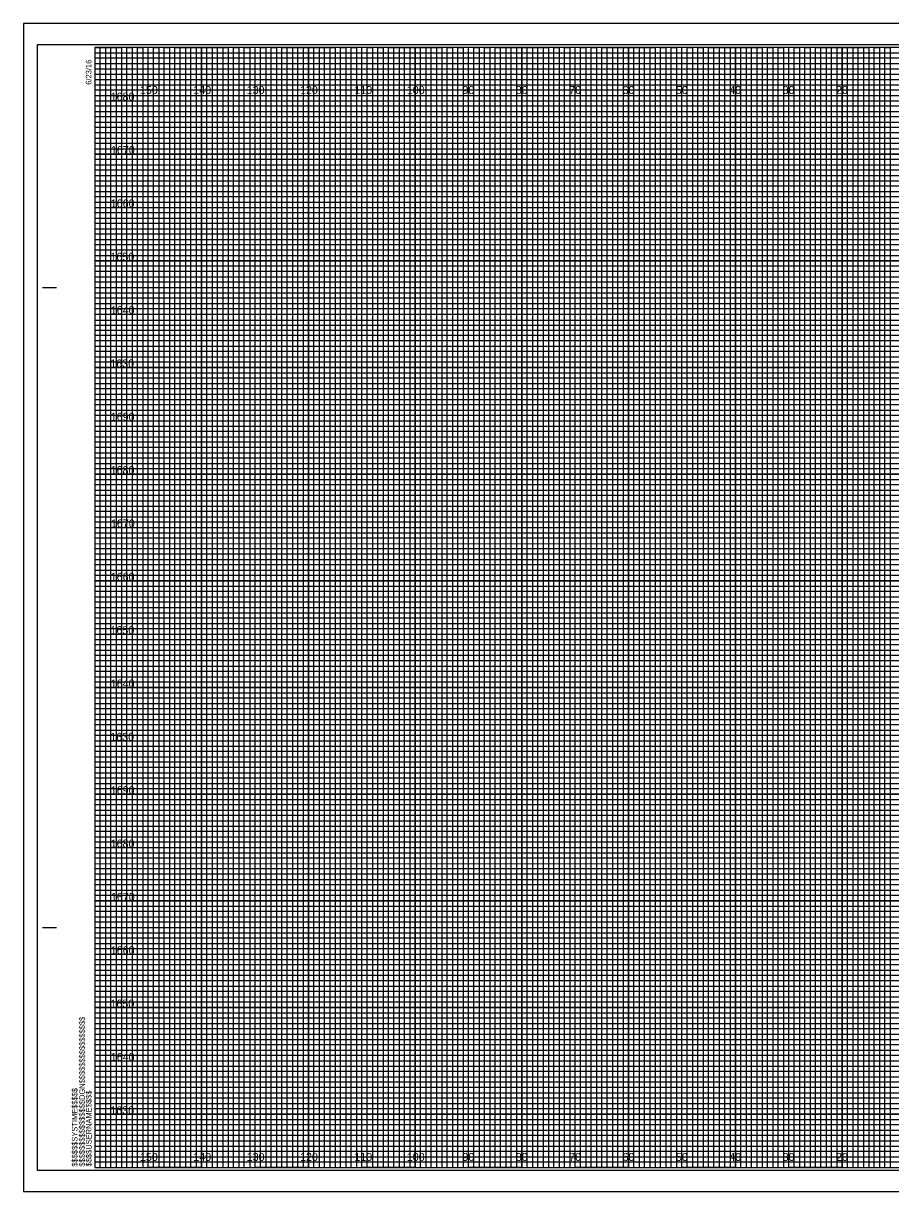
# Model space of a CAD drawing. Extents: x -13 to 323, y -5 to 2414.
# Drawn here: x -13.4 to 149.1, y 655.5 to 874.5 of the extents above; entities that cross this region are included whole.
import ezdxf

# ---------------------------------------------------------------- set-up
doc = ezdxf.new("R2010")
doc.units = 0
for name, color, linetype in [('Prop XS Elevation Labels', 7, 'Continuous'), ('Prop XS Offset Labels', 7, 'Continuous'), ('Sheet Cross Section CELL', 7, 'Continuous'), ('Sheet Cross Section Grid Major CELL', 7, 'Continuous'), ('Sheet Cross Section Grid Middle CELL', 7, 'Continuous'), ('Sheet Cross Section Grid Minor 1 CELL', 7, 'Continuous'), ('Sheet Cross Section Grid Minor 2 CELL', 7, 'Continuous'), ('Sheet Cutting Line CELL', 7, 'Continuous'), ('Sheet DOT Grid CELL', 7, 'Continuous'), ('Sheet Plot Border Inside CELL', 7, 'Continuous'), ('Sheet Plot Border Outside CELL', 7, 'Continuous')]:
    doc.layers.add(name, color=color, linetype=linetype)

msp = doc.modelspace()

# ---------------------------------------------------------------- linework, layer by layer
at = {"layer": 'Sheet Cross Section CELL'}
for p, q in [((-9.8, 825), (-7.3, 825)), ((-9.7, 825), (-7.2, 825)), ((-9.8, 705), (-7.3, 705)), ((-9.7, 705), (-7.2, 705)), ((0, 660), (0, 660)), ((0, 660), (0, 660)), ((0, 660), (0, 660)), ((0, 660), (0, 660)), ((0, 660), (0, 660)), ((0, 660), (0, 660)), ((0, 660), (0, 660))]:
    msp.add_line(p, q, dxfattribs=at)
msp.add_lwpolyline([(320, 870), (0, 870), (0, 660), (320, 660)], close=True, dxfattribs=at)
at = {"layer": 'Sheet Cross Section Grid Major CELL'}
for p, q in [((10, 870), (0, 870)), ((10, 660), (10, 870)), ((30, 870), (20, 870)), ((20, 870), (20, 660)), ((30, 660), (30, 870)), ((50, 870), (40, 870)), ((40, 870), (40, 660)), ((50, 660), (50, 870)), ((70, 870), (60, 870)), ((60, 870), (60, 660)), ((70, 660), (70, 870)), ((90, 870), (80, 870)), ((80, 870), (80, 660)), ((90, 660), (90, 870)), ((110, 870), (100, 870)), ((100, 870), (100, 660)), ((110, 660), (110, 870)), ((130, 870), (120, 870)), ((120, 870), (120, 660)), ((130, 660), (130, 870)), ((150, 870), (140, 870)), ((140, 870), (140, 660)), ((20, 660), (10, 660)), ((40, 660), (30, 660)), ((60, 660), (50, 660)), ((80, 660), (70, 660)), ((100, 660), (90, 660)), ((120, 660), (110, 660)), ((140, 660), (130, 660))]:
    msp.add_line(p, q, dxfattribs=at)
for points in [[(0, 860), (320, 860), (320, 850), (0, 850)], [(0, 840), (320, 840), (320, 830), (0, 830)], [(0, 820), (320, 820), (320, 810), (0, 810)], [(0, 800), (320, 800), (320, 790), (0, 790)], [(0, 780), (320, 780), (320, 770), (0, 770)], [(0, 760), (320, 760), (320, 750), (0, 750)], [(0, 740), (320, 740), (320, 730), (0, 730)], [(0, 720), (320, 720), (320, 710), (0, 710)], [(0, 700), (320, 700), (320, 690), (0, 690)], [(0, 680), (320, 680), (320, 670), (0, 670)]]:
    msp.add_lwpolyline(points, dxfattribs=at)
at = {"layer": 'Sheet Cross Section Grid Middle CELL'}
for points in [[(0, 870), (5, 870), (5, 660), (15, 660), (15, 870), (25, 870), (25, 660), (35, 660), (35, 870), (45, 870), (45, 660), (55, 660), (55, 870), (65, 870), (65, 660), (75, 660), (75, 870), (85, 870), (85, 660), (95, 660), (95, 870), (105, 870), (105, 660), (115, 660), (115, 870), (125, 870), (125, 660), (135, 660), (135, 870), (145, 870), (145, 660), (155, 660)], [(0, 865), (275, 865)], [(0, 845), (320, 845), (320, 855), (0, 855)], [(0, 825), (320, 825), (320, 835), (0, 835)], [(0, 805), (320, 805), (320, 815), (0, 815)], [(0, 785), (320, 785), (320, 795), (0, 795)], [(0, 765), (320, 765), (320, 775), (0, 775)], [(0, 745), (320, 745), (320, 755), (0, 755)], [(0, 725), (320, 725), (320, 735), (0, 735)], [(0, 705), (320, 705), (320, 715), (0, 715)], [(0, 685), (320, 685), (320, 695), (0, 695)], [(0, 665), (320, 665), (320, 675), (0, 675)]]:
    msp.add_lwpolyline(points, dxfattribs=at)
at = {"layer": 'Sheet Cross Section Grid Minor 1 CELL'}
for p, q in [((0, 869), (260, 869)), ((260, 867.98), (0, 867.98)), ((0, 867.98), (0, 867)), ((0, 867), (260, 867)), ((260, 865.89), (0, 865.89)), ((0, 865.89), (0, 864)), ((0, 864), (320, 864))]:
    msp.add_line(p, q, dxfattribs=at)
for points in [[(0, 863), (270, 863), (320, 863), (320, 862), (0, 862)], [(0, 861), (320, 861), (320, 859), (0, 859)], [(0, 858), (320, 858), (320, 857), (0, 856.98)], [(0, 856), (320, 856), (320, 854), (0, 854)], [(0, 853), (320, 853), (320, 852), (0, 852)], [(0, 851), (320, 851), (320, 849), (0, 849)], [(0, 848), (320, 848), (320, 847), (0, 847)], [(0, 846), (320, 846), (320, 844), (0, 844)], [(0, 843), (320, 843), (320, 842), (0, 842)], [(0, 841), (320, 841), (320, 839), (0, 839)], [(0, 838), (320, 838), (320, 837), (0, 837)], [(0, 836), (320, 836), (320, 833.95), (320, 833), (320, 832), (0, 832)], [(0, 834), (320, 834), (320, 833), (0, 833)], [(0, 831), (320, 831), (320, 829), (0, 829.03)], [(0, 829.03), (320, 829), (320, 828), (0, 828)], [(0, 827), (320, 827), (320, 826), (0, 826)], [(0, 824), (320, 824), (320, 823), (0, 823)], [(0, 822), (320, 822), (320, 821), (0, 821)], [(-0.07, 818.89), (320, 818.89), (320, 817.88), (-0.07, 817.88)], [(0, 817), (320, 817), (320, 816), (0, 816)], [(0, 814), (320, 814), (320, 813), (0, 813)], [(0, 812), (320, 812), (320, 811), (0, 811)], [(0, 809), (320, 809), (320, 808), (0, 808)], [(0, 807), (320, 807), (320, 806), (0, 806)], [(0, 804), (320, 804), (320, 803), (0, 803)], [(0, 802), (320, 802), (320, 801), (0, 801)], [(0, 799), (320, 799), (319.99, 797.98), (0, 798)], [(0, 797), (320, 797), (320, 796), (0, 796)], [(0, 794), (320, 794), (320, 793), (0, 793)], [(0, 792), (320, 792), (320, 791), (0, 791)], [(0, 789), (320, 789), (320, 788), (0, 788)], [(0, 787), (320, 787), (320, 786), (0, 786)], [(0, 784), (320, 784), (320, 783), (0, 783)], [(0, 782), (320, 782), (320, 781), (0, 781)], [(0, 779), (320, 779), (320, 778), (0, 778)], [(0, 776.99), (320.07, 776.91), (320, 776), (0, 776)], [(0, 774), (320, 774), (320, 773), (0, 773)], [(0, 772), (320, 772), (320, 771), (0, 771)], [(0, 769), (320, 769), (320, 768), (0, 768)], [(0, 767), (320, 767), (320, 766), (0, 766)], [(0, 764), (320, 764), (320, 763), (0, 763)], [(0, 762), (320, 762), (320, 761), (0, 761)], [(0, 759), (320, 759), (320, 758), (0, 758)], [(0, 757), (320, 757), (320, 756), (0, 756)], [(0, 754), (320, 754), (320, 753), (0, 753)], [(0, 752), (320, 752), (320, 751), (0, 751)], [(0, 749), (320, 749), (320, 748), (0, 748)], [(0, 747), (320, 747), (320, 746), (0, 746)], [(0, 744), (320, 744), (320, 743), (0, 743)], [(0, 742), (320, 742), (320, 741), (0, 741)], [(0, 739), (320, 739), (319.99, 737.98), (0, 738)], [(0, 737), (320, 737), (320, 736), (0, 736)], [(0, 734), (320, 734), (320, 733), (0, 733)], [(0, 732), (320, 732), (320, 731), (0, 731)], [(0, 729), (320, 729), (320, 728), (0, 728)], [(0, 727), (320, 727), (320, 726), (0, 726)], [(0, 724), (320, 724), (320, 723), (0, 723)], [(0, 722), (320, 722), (320, 721), (0, 721)], [(0, 719), (320, 719), (320, 718), (0, 718)], [(0, 716.99), (320.07, 716.91), (320, 716), (0, 716)], [(0, 714), (320, 714), (320, 713), (0, 713)], [(0, 712), (320, 712), (320, 711), (0, 711)], [(0, 709), (320, 709), (320, 708), (0, 708)], [(0, 707), (320, 707), (320, 706), (0, 706)], [(0, 704), (320, 704), (320, 703), (0, 703)], [(0, 702), (320, 702), (320, 701), (0, 701)], [(0, 699), (320, 699), (320, 698), (0, 698)], [(0, 697), (320, 697), (320, 696), (0, 696)], [(0, 694), (320, 694), (320, 693), (0, 693)], [(0, 692), (320, 692), (320, 691), (0, 691)], [(0, 689), (320, 689), (320, 688), (0, 688)], [(0, 687), (320, 687), (320, 686), (0, 686)], [(0, 684), (320, 684), (320, 683), (0, 683)], [(0, 682), (320, 682), (320, 681), (0, 681)], [(0, 679), (320, 679), (320, 678), (0, 678)], [(0, 677), (320, 677), (320, 676), (0, 676)], [(0, 674), (320, 674), (320, 673), (0, 673)], [(0, 672), (320, 672), (320, 671), (0, 671)], [(0, 669), (320, 669), (320, 668), (0, 668)], [(0, 667), (320, 667), (320, 666), (0, 666)], [(0, 664), (320, 664), (320, 663), (0, 663)], [(0, 662), (320, 662), (320, 661), (0, 661)]]:
    msp.add_lwpolyline(points, dxfattribs=at)
at = {"layer": 'Sheet Cross Section Grid Minor 2 CELL'}
for points in [[(0, 660), (1, 660), (1, 870), (2, 870), (2, 660)], [(2, 660), (3, 660), (3, 870), (4, 870), (4, 660)], [(5, 660), (6, 660), (6, 870), (7, 870), (7, 660)], [(7, 660), (8, 660), (8, 870), (9, 870), (9, 660)], [(10, 660), (11, 660), (11, 870), (12, 870), (12, 660)], [(12, 660), (13, 660), (13, 870), (14, 870), (14, 660)], [(15, 660), (16, 660), (16, 870), (17, 870), (17, 660)], [(17, 660), (18, 660), (18, 870), (19, 870), (19, 660)], [(20, 660), (21, 660), (21, 870), (22, 870), (22, 660)], [(22, 660), (23, 660), (23, 870), (24, 870), (24, 660)], [(25, 660), (26, 660), (26, 870), (27, 870), (27, 660)], [(27, 660), (28, 660), (28, 870), (29, 870), (29, 660)], [(30, 660), (31, 660), (31, 870), (32, 870), (32, 660)], [(32, 660), (33, 660), (33, 870), (34, 870), (34, 660)], [(35, 660), (36, 660), (36, 870), (37, 870), (37, 660)], [(37, 660), (38, 660), (38, 870), (39, 870), (39, 660)], [(40, 660), (41, 660), (41, 870), (42, 870), (42, 660)], [(42, 660), (43, 660), (43, 870), (44, 870), (44, 660)], [(45, 660), (46, 660), (46, 870), (47, 870), (47, 660)], [(47, 660), (48, 660), (48, 870), (49, 870), (49, 660)], [(50, 660), (51, 660), (51, 870), (52, 870), (52, 660)], [(52, 660), (53, 660), (53, 870), (54, 870), (54, 660)], [(55, 660), (56, 660), (56, 870), (57, 870), (57, 660)], [(57, 660), (58, 660), (58, 870), (59, 870), (59, 660)], [(60, 660), (61, 660), (61, 870), (62, 870), (62, 660)], [(62, 660), (63, 660), (63, 870), (64, 870), (64, 660)], [(65, 660), (66, 660), (66, 870), (67, 870), (67, 660)], [(67, 660), (68, 660), (68, 870), (69, 870), (69, 660)], [(70, 660), (71, 660), (71, 870), (72, 870), (72, 660)], [(72, 660), (73, 660), (73, 870), (74, 870), (74, 660)], [(75, 660), (76, 660), (76, 870), (77, 870), (77, 660)], [(77, 660), (78, 660), (78, 870), (79, 870), (79, 660)], [(80, 660), (81, 660), (81, 870), (82, 870), (82, 660)], [(82, 660), (83, 660), (83, 870), (84, 870), (84, 660)], [(85, 660), (86, 660), (86, 870), (87, 870), (87, 660)], [(87, 660), (88, 660), (88, 870), (89, 870), (89, 660)], [(90, 660), (91, 660), (91, 870), (92, 870), (92, 660)], [(92, 660), (93, 660), (93, 870), (94, 870), (94, 660)], [(95, 660), (96, 660), (96, 870), (97, 870), (97, 660)], [(97, 660), (98, 660), (98, 870), (99, 870), (99, 660)], [(100, 660), (101, 660), (101, 870), (102, 870), (102, 660)], [(102, 660), (103, 660), (103, 870), (104, 870), (104, 660)], [(105, 660), (106, 660), (106, 870), (107, 870), (107, 660)], [(107, 660), (108, 660), (108, 870), (109, 870), (109, 660)], [(110, 660), (111, 660), (111, 870), (112, 870), (112, 660)], [(112, 660), (113, 660), (113, 870), (114, 870), (114, 660)], [(115, 660), (116, 660), (116, 870), (117, 870), (117, 660)], [(117, 660), (118, 660), (118, 870), (119, 870), (119, 660)], [(120, 660), (121, 660), (121, 870), (122, 870), (122, 660)], [(122, 660), (123, 660), (123, 870), (124, 870), (124, 660)], [(125, 660), (126, 660), (126, 870), (127, 870), (127, 660)], [(127, 660), (128, 660), (128, 870), (129, 870), (129, 660)], [(130, 660), (131, 660), (131, 870), (132, 870), (132, 660)], [(132, 660), (133, 660), (133, 870), (134, 870), (134, 660)], [(135, 660), (136, 660), (136, 870), (137, 870), (137, 660)], [(137, 660), (138, 660), (138, 870), (139, 870), (139, 660)], [(140, 660), (141, 660), (141, 870), (142, 870), (142, 660)], [(142, 660), (143, 660), (143, 870), (144, 870), (144, 660)], [(145, 660), (146, 660), (146, 870), (147, 870), (147, 660)], [(147, 660), (148, 660), (148, 870), (149, 870), (149, 660)]]:
    msp.add_lwpolyline(points, dxfattribs=at)
at = {"layer": 'Sheet Cutting Line CELL'}
for p, q in [((323.3, 874.5), (-13.4, 874.5)), ((-13.4, 874.5), (-13.4, 655.5)), ((-13.4, 655.5), (323.3, 655.5))]:
    msp.add_line(p, q, dxfattribs=at)
at = {"layer": 'Sheet DOT Grid CELL'}
for p, q in [((10, 660), (10, 870)), ((20, 660), (20, 870)), ((30, 660), (30, 870)), ((40, 660), (40, 870)), ((50, 660), (50, 870)), ((60, 660), (60, 870)), ((70, 660), (70, 870)), ((80, 660), (80, 870)), ((90, 660), (90, 870)), ((100, 660), (100, 870)), ((110, 660), (110, 870)), ((120, 660), (120, 870)), ((130, 660), (130, 870)), ((140, 660), (140, 870)), ((0, 860), (320, 860)), ((0, 850), (320, 850)), ((0, 840), (320, 840)), ((0, 830), (320, 830)), ((0, 820), (320, 820)), ((0, 810), (320, 810)), ((0, 800), (320, 800)), ((0, 790), (320, 790)), ((0, 780), (320, 780)), ((0, 770), (320, 770)), ((0, 760), (320, 760)), ((0, 750), (320, 750)), ((0, 740), (320, 740)), ((0, 730), (320, 730)), ((0, 720), (320, 720)), ((0, 710), (320, 710)), ((0, 700), (320, 700)), ((0, 690), (320, 690)), ((0, 680), (320, 680)), ((0, 670), (320, 670))]:
    msp.add_line(p, q, dxfattribs=at)
at = {"layer": 'Sheet Plot Border Inside CELL'}
msp.add_lwpolyline([(-10.8, 659.5), (322.4, 659.5), (322.4, 870.5), (-10.8, 870.5)], close=True, dxfattribs=at)
at = {"layer": 'Sheet Plot Border Outside CELL'}
msp.add_lwpolyline([(-13.4, 655.5), (323.3, 655.5), (323.3, 874.5), (-13.4, 874.5)], close=True, dxfattribs=at)

# ---------------------------------------------------------------- texts
at = {"layer": 'Prop XS Elevation Labels'}
for s, p in [('1680', (2.95, 860)), ('1670', (3, 850)), ('1660', (2.97, 840)), ('1650', (2.92, 830)), ('1640', (2.97, 820)), ('1630', (2.89, 810)), ('1690', (2.97, 800)), ('1680', (2.95, 790)), ('1670', (3, 780)), ('1660', (2.97, 770)), ('1650', (2.92, 760)), ('1640', (2.97, 750)), ('1630', (2.89, 740)), ('1690', (2.97, 730)), ('1680', (2.95, 720)), ('1670', (3, 710)), ('1660', (2.97, 700)), ('1650', (2.92, 690)), ('1640', (2.97, 680)), ('1630', (2.89, 670))]:
    msp.add_text(s, height=1.5, dxfattribs=at).set_placement(p)
at = {"layer": 'Prop XS Offset Labels'}
for s, p in [('150', (8.44, 861.25)), ('140', (18.44, 861.25)), ('130', (28.44, 861.25)), ('120', (38.44, 861.25)), ('110', (48.62, 861.25)), ('100', (58.44, 861.25)), ('90', (68.86, 861.25)), ('80', (78.86, 861.25)), ('70', (88.86, 861.25)), ('60', (98.86, 861.25)), ('50', (108.86, 861.25)), ('40', (118.86, 861.25)), ('30', (128.86, 861.25)), ('20', (138.86, 861.25)), ('150', (8.44, 661.25)), ('140', (18.44, 661.25)), ('130', (28.44, 661.25)), ('120', (38.44, 661.25)), ('110', (48.62, 661.25)), ('100', (58.44, 661.25)), ('90', (68.86, 661.25)), ('80', (78.86, 661.25)), ('70', (88.86, 661.25)), ('60', (98.86, 661.25)), ('50', (108.86, 661.25)), ('40', (118.86, 661.25)), ('30', (128.86, 661.25)), ('20', (138.86, 661.25))]:
    msp.add_text(s, height=1.5, dxfattribs=at).set_placement(p)
at = {"layer": 'Sheet Cross Section CELL'}
for s, p in [('6/23/16', (-0.65, 863)), ('$$$$$$$$$$$$$$$$DGN$$$$$$$$$$$$$$$$', (-1.88, 660.18)), ('$$$$$$SYSTIME$$$$$', (-3.26, 660.18)), ('$$$$USERNAME$$$$', (-0.62, 660.23))]:
    msp.add_text(s, height=1.05, rotation=90, dxfattribs=at).set_placement(p)

doc.saveas('drawing.dxf')
